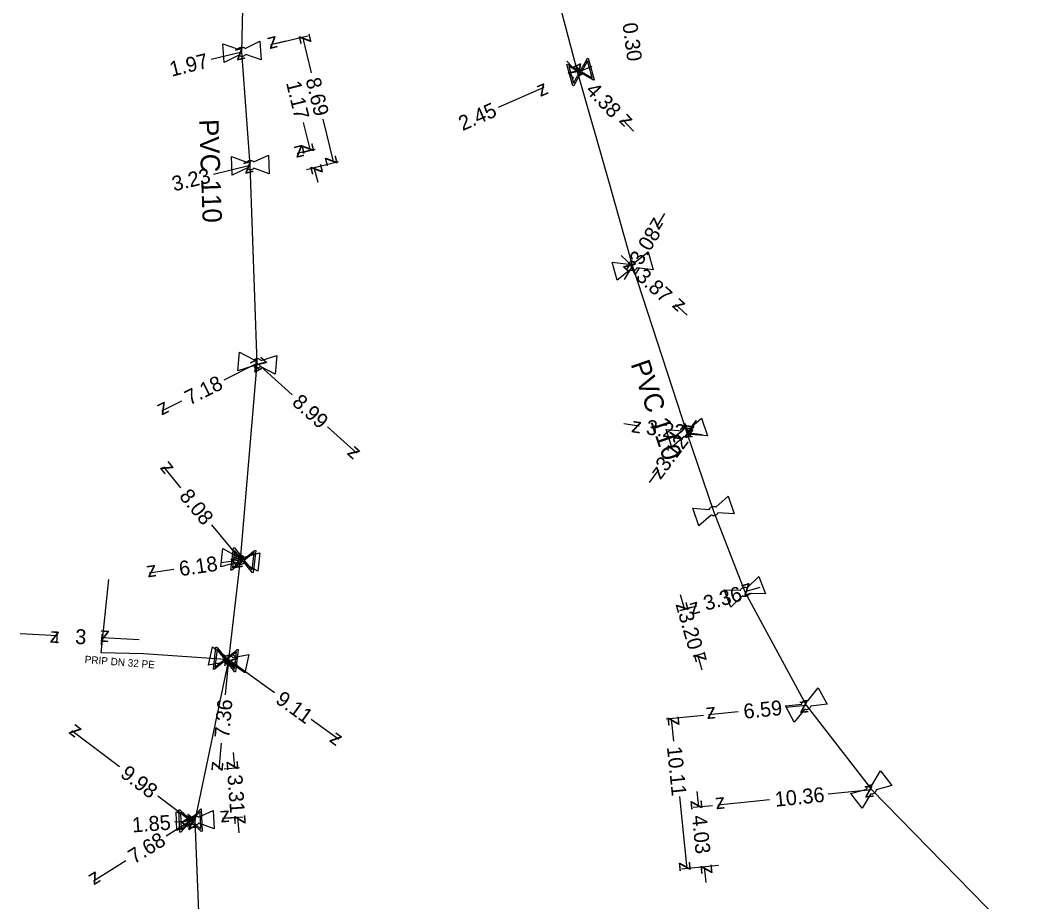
# Model space of a CAD drawing. Extents: x -638315 to -636370, y -1116147 to -1115110.
# Drawn here: x -637132.1 to -637064.4, y -1115828.9 to -1115769.8 of the extents above; entities that cross this region are included whole.
import ezdxf

# ---------------------------------------------------------------- set-up
doc = ezdxf.new("R2010")
doc.units = 0
for name, color, linetype in [('Default', 7, 'Continuous'), ('VP Kótování', 7, 'Continuous'), ('VP Lomový bod', 7, 'Continuous'), ('VP Popis přípojky', 7, 'Continuous'), ('VP Přípojka', 7, 'Continuous'), ('VP Řad', 7, 'Continuous'), ('VP Řad - popis', 7, 'Continuous'), ('VP Šoupě', 7, 'Continuous')]:
    doc.layers.add(name, color=color, linetype=linetype)

msp = doc.modelspace()

# ---------------------------------------------------------------- linework, layer by layer
at = {"layer": 'Default'}
for points in [[(-637117.451, -1115771.694), (-637117.42, -1115771.651), (-637117.374, -1115771.621), (-637117.304, -1115771.574), (-637117.222, -1115771.568), (-637117.141, -1115771.562), (-637117.062, -1115771.599), (-637117.014, -1115771.621), (-637116.977, -1115771.659)], [(-637116.947, -1115772.067), (-637116.978, -1115772.108), (-637117.023, -1115772.138), (-637117.095, -1115772.185), (-637117.177, -1115772.191), (-637117.258, -1115772.197), (-637117.334, -1115772.161), (-637117.384, -1115772.138), (-637117.421, -1115772.1)], [(-637116.883, -1115779.285), (-637116.851, -1115779.243), (-637116.804, -1115779.215), (-637116.732, -1115779.171), (-637116.651, -1115779.168), (-637116.569, -1115779.165), (-637116.492, -1115779.205), (-637116.445, -1115779.229), (-637116.409, -1115779.268)], [(-637116.394, -1115779.677), (-637116.427, -1115779.717), (-637116.473, -1115779.745), (-637116.547, -1115779.789), (-637116.629, -1115779.792), (-637116.71, -1115779.795), (-637116.785, -1115779.756), (-637116.833, -1115779.731), (-637116.869, -1115779.692)], [(-637091.264, -1115786.118), (-637091.242, -1115786.07), (-637091.204, -1115786.032), (-637091.145, -1115785.972), (-637091.066, -1115785.949), (-637090.987, -1115785.927), (-637090.903, -1115785.947), (-637090.851, -1115785.959), (-637090.807, -1115785.988)], [(-637090.695, -1115786.382), (-637090.717, -1115786.429), (-637090.755, -1115786.467), (-637090.816, -1115786.528), (-637090.895, -1115786.55), (-637090.973, -1115786.573), (-637091.055, -1115786.553), (-637091.108, -1115786.54), (-637091.152, -1115786.511)], [(-637115.952, -1115792.994), (-637115.989, -1115793.031), (-637116.039, -1115793.054), (-637116.115, -1115793.089), (-637116.197, -1115793.082), (-637116.278, -1115793.074), (-637116.35, -1115793.025), (-637116.394, -1115792.996), (-637116.425, -1115792.953)], [(-637116.389, -1115792.545), (-637116.352, -1115792.509), (-637116.304, -1115792.487), (-637116.225, -1115792.452), (-637116.143, -1115792.459), (-637116.062, -1115792.466), (-637115.992, -1115792.514), (-637115.947, -1115792.544), (-637115.916, -1115792.587)], [(-637087.638, -1115797.309), (-637087.618, -1115797.26), (-637087.581, -1115797.22), (-637087.524, -1115797.158), (-637087.447, -1115797.133), (-637087.369, -1115797.107), (-637087.284, -1115797.125), (-637087.232, -1115797.135), (-637087.187, -1115797.162)], [(-637087.06, -1115797.551), (-637087.081, -1115797.599), (-637087.117, -1115797.639), (-637087.176, -1115797.702), (-637087.254, -1115797.727), (-637087.331, -1115797.752), (-637087.414, -1115797.736), (-637087.467, -1115797.725), (-637087.512, -1115797.697)], [(-637085.84, -1115802.574), (-637085.82, -1115802.525), (-637085.784, -1115802.484), (-637085.728, -1115802.421), (-637085.651, -1115802.394), (-637085.573, -1115802.368), (-637085.488, -1115802.384), (-637085.436, -1115802.393), (-637085.39, -1115802.42)], [(-637085.258, -1115802.807), (-637085.278, -1115802.855), (-637085.313, -1115802.895), (-637085.371, -1115802.959), (-637085.448, -1115802.986), (-637085.526, -1115803.012), (-637085.609, -1115802.997), (-637085.662, -1115802.987), (-637085.708, -1115802.96)], [(-637117.521, -1115805.729), (-637117.483, -1115805.694), (-637117.433, -1115805.673), (-637117.353, -1115805.64), (-637117.272, -1115805.65), (-637117.191, -1115805.659), (-637117.123, -1115805.709), (-637117.079, -1115805.741), (-637117.049, -1115805.785)], [(-637117.097, -1115806.19), (-637117.135, -1115806.226), (-637117.186, -1115806.247), (-637117.263, -1115806.28), (-637117.345, -1115806.271), (-637117.426, -1115806.261), (-637117.496, -1115806.21), (-637117.539, -1115806.179), (-637117.568, -1115806.135)], [(-637083.744, -1115808.005), (-637083.727, -1115807.956), (-637083.692, -1115807.913), (-637083.639, -1115807.848), (-637083.563, -1115807.819), (-637083.486, -1115807.789), (-637083.4, -1115807.802), (-637083.348, -1115807.809), (-637083.302, -1115807.834)], [(-637083.154, -1115808.215), (-637083.172, -1115808.264), (-637083.205, -1115808.306), (-637083.261, -1115808.372), (-637083.337, -1115808.401), (-637083.413, -1115808.431), (-637083.496, -1115808.419), (-637083.551, -1115808.411), (-637083.597, -1115808.386)], [(-637118.284, -1115812.425), (-637118.242, -1115812.393), (-637118.191, -1115812.377), (-637118.109, -1115812.351), (-637118.029, -1115812.368), (-637117.949, -1115812.385), (-637117.886, -1115812.441), (-637117.845, -1115812.477), (-637117.819, -1115812.523)], [(-637117.903, -1115812.922), (-637117.945, -1115812.955), (-637117.997, -1115812.971), (-637118.077, -1115812.997), (-637118.157, -1115812.98), (-637118.237, -1115812.963), (-637118.302, -1115812.906), (-637118.343, -1115812.871), (-637118.368, -1115812.825)], [(-637079.635, -1115815.634), (-637079.625, -1115815.582), (-637079.596, -1115815.536), (-637079.551, -1115815.465), (-637079.479, -1115815.426), (-637079.407, -1115815.387), (-637079.32, -1115815.388), (-637079.267, -1115815.388), (-637079.218, -1115815.408)], [(-637079.023, -1115815.767), (-637079.034, -1115815.818), (-637079.062, -1115815.863), (-637079.109, -1115815.936), (-637079.181, -1115815.975), (-637079.253, -1115816.014), (-637079.337, -1115816.012), (-637079.392, -1115816.011), (-637079.441, -1115815.992)], [(-637075.272, -1115821.353), (-637075.269, -1115821.3), (-637075.248, -1115821.25), (-637075.215, -1115821.172), (-637075.151, -1115821.122), (-637075.086, -1115821.073), (-637075, -1115821.06), (-637074.947, -1115821.052), (-637074.896, -1115821.063)], [(-637074.646, -1115821.387), (-637074.649, -1115821.439), (-637074.67, -1115821.489), (-637074.704, -1115821.568), (-637074.769, -1115821.618), (-637074.834, -1115821.667), (-637074.917, -1115821.679), (-637074.971, -1115821.687), (-637075.023, -1115821.676)], [(-637120.595, -1115823.246), (-637120.562, -1115823.204), (-637120.516, -1115823.175), (-637120.444, -1115823.131), (-637120.362, -1115823.127), (-637120.281, -1115823.124), (-637120.203, -1115823.164), (-637120.156, -1115823.188), (-637120.12, -1115823.226)], [(-637120.104, -1115823.635), (-637120.136, -1115823.675), (-637120.181, -1115823.704), (-637120.255, -1115823.749), (-637120.337, -1115823.752), (-637120.419, -1115823.755), (-637120.494, -1115823.717), (-637120.542, -1115823.692), (-637120.578, -1115823.653)]]:
    msp.add_open_spline(points, degree=3, dxfattribs=at)
at = {"layer": 'VP Kótování'}
for points in [[(-637114.265, -1115771.161), (-637115.285, -1115771.411)], [(-637114.945, -1115771.328), (-637112.781, -1115770.798)], [(-637112.533, -1115773.285), (-637113.121, -1115770.881)], [(-637119.262, -1115772.385), (-637117.2, -1115771.88)], [(-637095.402, -1115772.518), (-637094.676, -1115773.277)], [(-637093.714, -1115772.856), (-637094.676, -1115773.277)], [(-637099.976, -1115775.598), (-637096.92, -1115774.26)], [(-637113.083, -1115776.624), (-637112.624, -1115778.497)], [(-637111.77, -1115776.402), (-637111.056, -1115779.32)], [(-637090.924, -1115777.199), (-637091.65, -1115776.44)], [(-637112.479, -1115778.461), (-637113.499, -1115778.711)], [(-637113.159, -1115778.628), (-637112.284, -1115778.413)], [(-637119.107, -1115780.084), (-637116.64, -1115779.48)], [(-637112.88, -1115779.767), (-637110.716, -1115779.237)], [(-637112.88, -1115779.767), (-637112.005, -1115779.552)], [(-637112.095, -1115780.655), (-637112.345, -1115779.636)], [(-637088.834, -1115782.723), (-637089.38, -1115783.62)], [(-637091.761, -1115785.548), (-637090.98, -1115786.25)], [(-637091.526, -1115787.147), (-637090.98, -1115786.25)], [(-637087.319, -1115789.542), (-637088.1, -1115788.84)], [(-637118.389, -1115793.883), (-637116.17, -1115792.77)], [(-637113.829, -1115794.887), (-637116.17, -1115792.77)], [(-637121.256, -1115795.321), (-637122.59, -1115795.99)], [(-637111.449, -1115797.038), (-637109.5, -1115798.8)], [(-637091.579, -1115796.82), (-637090.54, -1115796.97)], [(-637086.721, -1115796.589), (-637087.35, -1115797.43)], [(-637086.311, -1115797.58), (-637087.35, -1115797.43)], [(-637121.297, -1115801.127), (-637122.45, -1115799.73)], [(-637089.849, -1115800.771), (-637089.22, -1115799.93)], [(-637119.255, -1115803.602), (-637117.308, -1115805.96)], [(-637118.598, -1115806.15), (-637117.308, -1115805.96)], [(-637121.772, -1115806.617), (-637123.42, -1115806.86)], [(-637082.442, -1115807.818), (-637083.45, -1115808.11)], [(-637087.788, -1115808.275), (-637087.495, -1115809.283)], [(-637087.017, -1115809.144), (-637087.832, -1115809.381)], [(-637087.689, -1115809.339), (-637086.681, -1115809.047)], [(-637132.086, -1115810.91), (-637129.589, -1115811.037)], [(-637129.615, -1115811.541), (-637129.576, -1115810.788)], [(-637126.618, -1115811.693), (-637126.58, -1115810.94)], [(-637124.096, -1115811.316), (-637126.593, -1115811.19)], [(-637118.304, -1115815.026), (-637118.093, -1115812.674)], [(-637115.014, -1115814.888), (-637118.093, -1115812.674)], [(-637086.126, -1115812.217), (-637086.941, -1115812.454)], [(-637086.312, -1115813.365), (-637086.604, -1115812.356)], [(-637080.698, -1115815.839), (-637079.33, -1115815.7)], [(-637112.552, -1115816.659), (-637110.7, -1115817.99)], [(-637086.232, -1115816.402), (-637088.721, -1115816.656)], [(-637088.221, -1115818.12), (-637088.373, -1115816.62)], [(-637083.89, -1115816.164), (-637085.884, -1115816.367)], [(-637125.409, -1115819.851), (-637128.61, -1115817.43)], [(-637118.593, -1115818.254), (-637118.75, -1115820)], [(-637117.788, -1115818.877), (-637117.712, -1115819.924)], [(-637118.401, -1115819.974), (-637117.363, -1115819.898)], [(-637086.672, -1115821.505), (-637086.565, -1115822.55)], [(-637077.869, -1115821.666), (-637074.96, -1115821.37)], [(-637122.85, -1115821.786), (-637120.648, -1115823.452)], [(-637087.843, -1115821.834), (-637087.349, -1115826.683)], [(-637081.79, -1115822.064), (-637085.268, -1115822.418)], [(-637085.616, -1115822.453), (-637086.914, -1115822.585)], [(-637122.277, -1115824.465), (-637120.648, -1115823.452)], [(-637121.728, -1115823.541), (-637120.35, -1115823.44)], [(-637117.461, -1115823.228), (-637118.508, -1115823.305)], [(-637118.159, -1115823.279), (-637117.121, -1115823.203)], [(-637117.393, -1115824.276), (-637117.47, -1115823.229)], [(-637125.001, -1115826.16), (-637127.17, -1115827.51)], [(-637085.208, -1115826.465), (-637087.697, -1115826.719)], [(-637085.208, -1115826.465), (-637086.506, -1115826.597)], [(-637086.051, -1115827.607), (-637086.157, -1115826.562)]]:
    msp.add_lwpolyline(points, dxfattribs=at)
at = {"layer": 'VP Lomový bod'}
for points in [[(-637117.421, -1115772.1), (-637118.4, -1115772.595), (-637118.492, -1115771.348), (-637117.451, -1115771.694)], [(-637116.977, -1115771.659), (-637115.999, -1115771.165)], [(-637115.999, -1115771.165), (-637115.907, -1115772.411), (-637116.947, -1115772.067)], [(-637116.409, -1115779.268), (-637115.412, -1115778.811)], [(-637115.412, -1115778.811), (-637115.368, -1115780.06), (-637116.394, -1115779.677)], [(-637116.869, -1115779.692), (-637117.867, -1115780.149), (-637117.911, -1115778.9), (-637116.883, -1115779.285)], [(-637090.807, -1115785.988), (-637089.949, -1115785.306)], [(-637089.949, -1115785.306), (-637089.607, -1115786.508), (-637090.695, -1115786.382)], [(-637091.152, -1115786.511), (-637092.011, -1115787.193), (-637092.354, -1115785.991), (-637091.264, -1115786.118)], [(-637117.469, -1115793.285), (-637117.362, -1115792.04), (-637116.389, -1115792.545)], [(-637115.916, -1115792.587), (-637114.871, -1115792.255), (-637114.978, -1115793.5), (-637115.952, -1115792.994)], [(-637116.425, -1115792.953), (-637117.469, -1115793.285)], [(-637087.187, -1115797.162), (-637086.354, -1115796.449)], [(-637086.354, -1115796.449), (-637085.968, -1115797.638), (-637087.06, -1115797.551)], [(-637087.512, -1115797.697), (-637088.346, -1115798.41), (-637088.732, -1115797.221), (-637087.638, -1115797.309)], [(-637085.39, -1115802.42), (-637084.569, -1115801.694)], [(-637084.569, -1115801.694), (-637084.165, -1115802.877), (-637085.258, -1115802.807)], [(-637085.708, -1115802.96), (-637086.53, -1115803.686), (-637086.935, -1115802.503), (-637085.84, -1115802.574)], [(-637118.623, -1115806.436), (-637118.477, -1115805.194), (-637117.521, -1115805.729)], [(-637117.049, -1115805.785), (-637115.994, -1115805.485), (-637116.139, -1115806.726), (-637117.097, -1115806.19)], [(-637117.568, -1115806.135), (-637118.623, -1115806.436)], [(-637083.302, -1115807.834), (-637082.51, -1115807.076)], [(-637082.51, -1115807.076), (-637082.058, -1115808.241), (-637083.154, -1115808.215)], [(-637083.597, -1115808.386), (-637084.39, -1115809.144), (-637084.841, -1115807.979), (-637083.744, -1115808.005)], [(-637119.445, -1115813.029), (-637119.188, -1115811.806), (-637118.284, -1115812.425)], [(-637117.819, -1115812.523), (-637116.741, -1115812.319), (-637116.998, -1115813.542), (-637117.903, -1115812.922)], [(-637118.368, -1115812.825), (-637119.445, -1115813.029)], [(-637079.218, -1115815.408), (-637078.53, -1115814.555)], [(-637078.53, -1115814.555), (-637077.933, -1115815.653), (-637079.023, -1115815.767)], [(-637079.441, -1115815.992), (-637080.131, -1115816.846), (-637080.727, -1115815.747), (-637079.635, -1115815.634)], [(-637074.896, -1115821.063), (-637074.351, -1115820.112)], [(-637074.351, -1115820.112), (-637073.588, -1115821.102), (-637074.646, -1115821.387)], [(-637075.023, -1115821.676), (-637075.568, -1115822.628), (-637076.331, -1115821.638), (-637075.272, -1115821.353)], [(-637120.578, -1115823.653), (-637121.574, -1115824.114), (-637121.624, -1115822.865), (-637120.595, -1115823.246)], [(-637120.12, -1115823.226), (-637119.126, -1115822.765)], [(-637119.126, -1115822.765), (-637119.076, -1115824.014), (-637120.104, -1115823.635)]]:
    msp.add_lwpolyline(points, dxfattribs=at)
at = {"layer": 'VP Přípojka'}
for points in [[(-637094.676, -1115773.277), (-637094.48, -1115773.24)], [(-637117.308, -1115805.96), (-637117.11, -1115805.99)], [(-637118.093, -1115812.674), (-637118.29, -1115812.64), (-637123.8, -1115812.255), (-637126.644, -1115812.192), (-637126.13, -1115807.28)], [(-637120.648, -1115823.452), (-637120.35, -1115823.44)]]:
    msp.add_lwpolyline(points, dxfattribs=at)
at = {"layer": 'VP Řad'}
for points in [[(-637119.99, -1115832.377), (-637120.35, -1115823.44), (-637118.093, -1115812.674), (-637117.308, -1115805.96), (-637116.17, -1115792.77), (-637116.64, -1115779.48), (-637117.2, -1115771.88), (-637116.969, -1115761.358), (-637116.969, -1115761.353), (-637116.94, -1115760.02), (-637116.26, -1115753.03), (-637114.999, -1115747.795), (-637114.125, -1115744.164), (-637113.816, -1115743.418), (-637110.92, -1115734.14)], [(-637110.92, -1115734.14), (-637109.81, -1115734.58), (-637108.135, -1115738.107), (-637099.971, -1115755.301), (-637099.078, -1115758.192), (-637096.13, -1115767.74), (-637094.676, -1115773.277), (-637092.522, -1115780.838), (-637090.98, -1115786.25), (-637087.35, -1115797.43), (-637085.55, -1115802.69), (-637083.45, -1115808.11), (-637079.33, -1115815.7), (-637074.96, -1115821.37), (-637064.392, -1115832.177)]]:
    msp.add_lwpolyline(points, dxfattribs=at)
at = {"layer": 'VP Šoupě'}
for points in [[(-637093.964, -1115772.313), (-637093.553, -1115773.756), (-637093.617, -1115773.774), (-637093.727, -1115773.708), (-637094.462, -1115773.3), (-637094.933, -1115774.149), (-637094.996, -1115774.167), (-637095.407, -1115772.724), (-637095.344, -1115772.706), (-637094.496, -1115773.181), (-637094.088, -1115772.446), (-637094.028, -1115772.331), (-637093.964, -1115772.313)], [(-637094.011, -1115772.491), (-637094.419, -1115773.223), (-637093.687, -1115773.63), (-637094.011, -1115772.491)], [(-637094.948, -1115773.995), (-637094.538, -1115773.258), (-637095.274, -1115772.849), (-637094.948, -1115773.995)], [(-637116.278, -1115805.332), (-637116.452, -1115806.822), (-637116.518, -1115806.815), (-637116.594, -1115806.711), (-637117.116, -1115806.053), (-637117.877, -1115806.656), (-637117.942, -1115806.648), (-637117.768, -1115805.158), (-637117.702, -1115805.166), (-637117.101, -1115805.929), (-637116.443, -1115805.407), (-637116.343, -1115805.325), (-637116.278, -1115805.332)], [(-637117.831, -1115806.508), (-637117.17, -1115805.984), (-637117.693, -1115805.325), (-637117.831, -1115806.508)], [(-637116.389, -1115805.478), (-637117.047, -1115805.998), (-637116.527, -1115806.654), (-637116.389, -1115805.478)], [(-637117.458, -1115811.982), (-637117.632, -1115813.472), (-637117.698, -1115813.465), (-637117.774, -1115813.361), (-637118.296, -1115812.703), (-637119.057, -1115813.306), (-637119.122, -1115813.298), (-637118.948, -1115811.808), (-637118.882, -1115811.816), (-637118.281, -1115812.579), (-637117.623, -1115812.057), (-637117.523, -1115811.975), (-637117.458, -1115811.982)], [(-637119.011, -1115813.158), (-637118.35, -1115812.634), (-637118.873, -1115811.975), (-637119.011, -1115813.158)], [(-637117.569, -1115812.128), (-637118.227, -1115812.648), (-637117.707, -1115813.304), (-637117.569, -1115812.128)], [(-637119.929, -1115822.673), (-637119.868, -1115824.172), (-637119.934, -1115824.174), (-637120.026, -1115824.084), (-637120.644, -1115823.515), (-637121.301, -1115824.229), (-637121.367, -1115824.232), (-637121.427, -1115822.733), (-637121.362, -1115822.731), (-637120.649, -1115823.391), (-637120.08, -1115822.773), (-637119.994, -1115822.675), (-637119.929, -1115822.673)], [(-637121.279, -1115824.076), (-637120.709, -1115823.456), (-637121.327, -1115822.886), (-637121.279, -1115824.076)], [(-637120.016, -1115822.834), (-637120.584, -1115823.451), (-637119.968, -1115824.017), (-637120.016, -1115822.834)]]:
    msp.add_lwpolyline(points, dxfattribs=at)

# ---------------------------------------------------------------- texts
at = {"layer": 'VP Kótování'}
for s, rotation, p in [('0.30', 277.58184, (-637091.669, -1115769.99)), ('z', 103.74994, (-637112.516, -1115771.248)), ('z', 193.76134, (-637114.918, -1115770.806)), ('1.97', 13.76136, (-637121.919, -1115773.551)), ('z', 13.76136, (-637117.567, -1115772.485)), ('z', 313.73188, (-637095.383, -1115773.261)), ('z', 203.65615, (-637094.419, -1115772.618)), ('1.17', 283.76371, (-637114.248, -1115773.966)), ('8.69', 283.74996, (-637112.935, -1115773.744)), ('z', 23.65617, (-637097.177, -1115774.919)), ('4.38', 313.73192, (-637094.184, -1115774.514)), ('2.45', 23.65617, (-637102.395, -1115777.204)), ('z', 133.7319, (-637090.943, -1115776.456)), ('z', 193.75693, (-637113.132, -1115778.106)), ('z', 283.76367, (-637113.228, -1115778.13)), ('z', 283.74992, (-637111.66, -1115778.954)), ('z', 13.75695, (-637117.007, -1115780.085)), ('z', 103.76369, (-637111.74, -1115780.002)), ('3.23', 13.75695, (-637121.765, -1115781.249)), ('z', 238.68513, (-637089.547, -1115782.933)), ('3.08', 58.68514, (-637090.407, -1115786.27)), ('z', 318.03479, (-637091.686, -1115786.287)), ('z', 58.68514, (-637090.813, -1115786.937)), ('3.87', 318.03478, (-637090.829, -1115787.058)), ('z', 138.03476, (-637087.394, -1115788.803)), ('z', 137.88493, (-637115.464, -1115792.734)), ('z', 26.63641, (-637116.393, -1115793.441)), ('7.18', 26.63641, (-637120.719, -1115795.611)), ('8.99', 317.88489, (-637113.904, -1115795.492)), ('z', 206.63639, (-637122.367, -1115795.319)), ('z', 351.7945, (-637091.106, -1115797.394)), ('3.22', 351.79448, (-637090.12, -1115797.536)), ('z', 233.20352, (-637087.451, -1115796.73)), ('z', 171.79446, (-637086.784, -1115797.006)), ('3.12', 53.20349, (-637088.729, -1115800.108)), ('z', 317.88491, (-637110.206, -1115798.836)), ('z', 129.53493, (-637121.746, -1115799.797)), ('z', 53.20349, (-637089.119, -1115800.63)), ('8.08', 309.53495, (-637121.46, -1115801.715)), ('6.18', 8.3767, (-637121.353, -1115807.061)), ('z', 309.53497, (-637118.012, -1115805.893)), ('z', 8.3767, (-637117.73, -1115806.528)), ('z', 188.37668, (-637122.998, -1115806.292)), ('3.36', 16.17231, (-637086.056, -1115809.386)), ('z', 196.17234, (-637083.109, -1115807.491)), ('z', 286.16923, (-637088.115, -1115808.942)), ('z', 16.17231, (-637087.022, -1115809.666)), ('3.20', 286.16921, (-637087.931, -1115809.578)), ('3', 357.0902, (-637128.414, -1115811.598)), ('z', 177.0902, (-637126.068, -1115810.716)), ('z', 357.0902, (-637130.114, -1115811.511)), ('z', 84.87539, (-637117.64, -1115813.217)), ('z', 144.28166, (-637117.395, -1115812.56)), ('z', 106.16925, (-637085.985, -1115812.697)), ('7.36', 84.87539, (-637118.064, -1115817.95)), ('9.11', 324.28168, (-637115.022, -1115815.498)), ('6.59', 5.811, (-637083.491, -1115816.626)), ('z', 5.811, (-637079.777, -1115816.248)), ('z', 185.81098, (-637085.437, -1115815.819)), ('z', 95.81035, (-637087.825, -1115817.067)), ('z', 142.89825, (-637127.91, -1115817.333)), ('z', 324.28164, (-637111.398, -1115818.104)), ('10.11', 275.81037, (-637088.683, -1115818.519)), ('z', 274.18788, (-637118.247, -1115819.462)), ('9.98', 322.89821, (-637125.431, -1115820.461)), ('z', 264.87537, (-637119.203, -1115819.457)), ('3.31', 274.18786, (-637118.179, -1115820.395)), ('10.36', 5.80521, (-637081.391, -1115822.526)), ('z', 5.80521, (-637075.407, -1115821.918)), ('z', 275.80672, (-637087.113, -1115822.103)), ('z', 185.80525, (-637084.821, -1115821.87)), ('z', 184.19168, (-637118.046, -1115822.77)), ('1.85', 4.1917, (-637124.544, -1115824.249)), ('z', 322.89823, (-637121.348, -1115823.549)), ('z', 31.88997, (-637120.808, -1115824.141)), ('z', 4.1917, (-637120.812, -1115823.975)), ('z', 94.18784, (-637116.935, -1115823.691)), ('4.03', 275.8067, (-637087.008, -1115823.138)), ('7.68', 31.88997, (-637124.439, -1115826.4)), ('z', 275.81038, (-637087.897, -1115826.236)), ('z', 211.88995, (-637127.01, -1115826.821)), ('z', 95.80674, (-637085.609, -1115827.009))]:
    msp.add_text(s, height=1, rotation=rotation, dxfattribs=at).set_placement(p)
at = {"layer": 'VP Popis přípojky'}
msp.add_text('PRIP DN 32 PE', height=0.5, rotation=355.55035, dxfattribs=at).set_placement((-637127.771, -1115812.883))
at = {"layer": 'VP Řad - popis'}
for rotation, p in [(272.02541, (-637120.079, -1115776.422)), (288.89122, (-637091.128, -1115792.818))]:
    msp.add_text('PVC 110', height=1.3, rotation=rotation, dxfattribs=at).set_placement(p)

doc.saveas('drawing.dxf')
